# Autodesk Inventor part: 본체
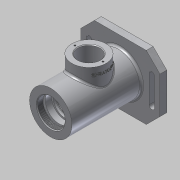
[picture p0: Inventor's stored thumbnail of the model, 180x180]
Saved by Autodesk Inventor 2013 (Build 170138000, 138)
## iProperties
Created: 2017-10
Part Number: 본체
Material: 알루미늄 6061
Document SubType Name: Modeling
Designer: Administrator
Density: 2.71 g/cm^3
Mass: 740.7 g
Surface Area: 652.727 cm^2
Volume: 273.321 cm^3
Author: Administrator
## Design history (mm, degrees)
sketch "스케치1"
  geometry: L1 (-58, 47)-(58, 47); L2 (58, 47)-(58, -47); L3 (58, -47)-(-58, -47); L4 (-58, -47)-(-58, 47); L5 (-58, 47)-(58, -47); L6 (58, 47)-(-58, -47); 1 further point
  constraints: 12 end point, 2 midpoint, 2 parallel, 1 horizontal, 1 perpendicular
  dimensions: "d3" = 116 distance of L2.end L3.end; "d4" = 94 distance of L1.end L2.end
extrude "돌출1" new body sketch "스케치1" distance "d5" = 10; taper "d6" = 0 deg
chamfer "모따기1" distance "d7" = 20; stored, may be unused: second distance "d8" = 2, angle "d9" = 45 deg
sketch "스케치2"
  geometry: L1 (31, 112)-(31, 10); L2 (27, 10)-(-27, 10) reference; L3 (0, 0)-(0, 188.497); L4 (-27, 0)-(27, 0) reference; L5 (47, 0)-(27, 0) reference; L6 (31, 112)-(21, 112); L7 (21, 112)-(21, 103); L8 (21, 103)-(24, 103); L9 (24, 103)-(24, 100); L10 (24, 100)-(20, 100); L11 (20, 100)-(20, 91); L12 (20, 91)-(17.5, 91); L13 (17.5, 91)-(17.5, 87.75); L14 (17.5, 87.75)-(18.5, 87.75); L15 (18.5, 87.75)-(18.5, 86); L16 (18.5, 86)-(17.5, 86); L17 (17.5, 86)-(17.5, 75); L18 (17.5, 75)-(26, 75); L19 (26, 75)-(26, 37); L20 (26, 37)-(17.5, 37); L21 (17.5, 37)-(17.5, 26.3); L22 (17.2, 26)-(16.5, 26); L23 (16.5, 26)-(16.5, 21); L24 (16.5, 21)-(10, 21); L25 (10, 21)-(10, 18.3); L26 (10, 18.3)-(12.2, 18.3); L27 (12.5, 18)-(12.5, 11.7); L28 (12.904, 11)-(16, 11); L29 (35, 0)-(35, -3); L30 (35, -3)-(0, -3); L31 (0, 0)-(0, -8.369); L32 (16, 11)-(22, -3); L33 (12.5, 11.7)-(12.904, 11); L34 (21, 112)-(0, 112); L35 (-47, 0)-(-47, 10) reference; L36 (-47, 10)-(47, 10) reference; L37 (47, 10)-(47, 0) reference; L38 (47, 0)-(-47, 0) reference; L39 (35, 0)-(31, 10); L40 (21, 103)-(0, 103); A1 r 0.3 centre (12.2, 18) between (12.5, 18) and (12.2, 18.3); A2 r 0.3 centre (17.2, 26.3) between (17.2, 26) and (17.5, 26.3)
  constraints: 66 end point, 23 parallel, 8 perpendicular, 6 point on line, 4 point on circle, 4 tangent, 2 centre point, 1 equal radius
  dimensions: "d10" = 62 diameter of L1 L3; "d14" = 42 diameter of L7 L3; "d15" = 48 diameter of L9 L3; "d16" = 40 diameter of L11 L3; "d17" = 35 diameter of L13 L3; "d18" = 37 diameter of L15 L3; "d19" = 35 diameter of L17 L3; "d20" = 52 diameter of L19 L3; "d21" = 35 diameter of L21 L3; "d22" = 33 diameter of L23 L3; "d23" = 20 diameter of L25 L3; "d24" = 25 diameter of L27 L3; "d25" = 32 diameter of L28.end L3; "d26" = 115 distance between parallel lines of L30 L6; "d27" = 44 diameter of L32.end L31; "d28" = 70 diameter of L29 L31; "d29" = 3 distance of L8.end L9.end; "d31" = 12 distance between parallel lines of L10 L6; "d32" = 21 distance between parallel lines of L12 L6; "d33" = 3 distance of L29.start L29.end; "d34" = 1.75 distance of L14.end L15.end; "d35" = 26 distance between parallel lines of L6 L16; "d36" = 11 distance of L16.end L17.end; "d37" = 38 distance of L18.end L19.end; "d38" = 14 distance between parallel lines of L30 L28; "d39" = 60 distance between parallel lines of L22 L16; "d40" = 5 distance of L22.end L23.end; "d42" = 2.7 distance of L24.end L25.end; "d43" = 30 deg angle of L27 L33; "d44" = 0.7 vertical distance of L28.start L27.end; "d45" = 0.3 radius of A1
  node "절단 모서리 투영1"
revolve "회전1" stored, may be unused: angle "d46" = 90 deg
revolve "회전2" stored, may be unused: angle "d47" = 90 deg
fillet "모깎기1" dims "d48" = 3
chamfer "모따기2" distance "d49" = 1; stored, may be unused: second distance "d50" = 2, angle "d51" = 45 deg
fillet "모깎기2" dims "d52" = 3
fillet "모깎기3" dims "d53" = 3
node "작업 평면1"
sketch "스케치3"
  geometry: L1 (38, 0)-(-38, 0) reference; L2 (-31, 112)-(31, 112) reference; C1 r 25 at (0, 56); 2 further points
  constraints: 1 centre point, 1 midpoint, 1 vertical alignment
  dimensions: "d55" = 56 distance from line of L2 C1.centre; "d56" = 50 diameter of C1
extrude "돌출2" join sketch "스케치3" stored distance "d57" = 10; taper "d58" = 0 deg
sketch "스케치4"
  geometry: C1 r 25 at (0, 0) reference; C2 r 16 at (0, 0); 1 further point
  constraints: 1 centre point, 1 coincident
  dimensions: "d59" = 32 diameter of C2
extrude "돌출3" cut sketch "스케치4" stored distance "d60" = 10; taper "d61" = 0 deg
chamfer "모따기4" distance "d65" = 1; stored, may be unused: second distance "d66" = 2, angle "d67" = 45 deg
fillet "모깎기4" dims "d68" = 3
sketch "스케치5"
  geometry: C1 r 25 at (0, 0) reference; C2 r 17 at (0, 0) reference; A1 r 20.5 centre (0, 0) between (-20.5, 0) and (20.5, 0); 1 further point
  constraints: 2 horizontal alignment, 2 point on circle, 1 centre point, 1 coincident
  dimensions: "d69" = 41 diameter of A1
hole "구멍1" sketch "스케치5" at (-20.5, 0), (20.5, 0) diameter "d70" = 2.459; stored, may be unused: countersink angle "d74" = 90 deg, drill point angle "d76" = 118 deg; dims "d71" = 6, "d72" = 4, "d73" = 2, "d75" = 8
sketch "스케치6"
  geometry: L1 (-42, 20)-(-42, -20); L2 (-50, 20)-(-50, -20); L3 (-38, 47)-(38, 47) reference; L4 (0, 0)-(0, 31); L5 (42, 20)-(42, -20); L6 (50, 20)-(50, -20); A1 r 4 centre (-46, 20) between (-42, 20) and (-50, 20); A2 r 4 centre (-46, -20) between (-50, -20) and (-42, -20); A3 r 4 centre (46, -20) between (42, -20) and (50, -20); A4 r 4 centre (46, 20) between (50, 20) and (42, 20)
  constraints: 10 end point, 8 point on circle, 6 symmetric about line, 4 centre point, 4 tangent, 1 equal radius, 1 perpendicular, 1 vertical, 1 vertical alignment, 3 other
  dimensions: "d79" = 46 horizontal distance of A2.centre L4.start; "d80" = 4 radius of A1; "d81" = 40 distance of A2.centre A1.centre; "d82" = 20 vertical distance of L4.start A1.centre
extrude "돌출4" cut sketch "스케치6" stored distance "d83" = 10; taper "d84" = 0 deg
node "작업 평면2"
sketch "스케치7"
  geometry: L1 (-78, 56)-(-16, 56) reference; L2 (0, 25)-(0, -25) reference; 2 further points
  constraints: 1 other
  dimensions: "d85" = 56 distance from line of L1 point (-10, 0); "d86" = 10 distance from line of L2 point (-10, 0)
feature "엠보싱1" sketch "스케치7" dims "d3" = 116, "d4" = 94, "d87" = 0.5, "d88" = 0
sketch "스케치8"
  geometry: C1 r 31 at (0, 0) reference; 1 further point
  constraints: 1 coincident
hole "구멍2" sketch "스케치8" at (0, 0) diameter "d89" = 40.376; stored, may be unused: countersink angle "d93" = 90 deg, drill point angle "d95" = 0 deg; dims "d90" = 6, "d91" = 4, "d92" = 2, "d94" = 9
fillet "모깎기5" dims "d96" = 3
chamfer "모따기5" distance "d97" = 1; stored, may be unused: second distance "d98" = 2, angle "d99" = 45 deg
node "솔리드1"
other parameters: "d54" = 47
